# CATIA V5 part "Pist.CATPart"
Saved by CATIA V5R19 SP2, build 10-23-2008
Part number: Pist
Bounding box of the stored display mesh (mm): x -20 to 20, y -20 to 20, z 0 to 180
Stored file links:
  D:\Catia\Flexible-rigid\Pist.CATPart
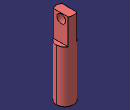
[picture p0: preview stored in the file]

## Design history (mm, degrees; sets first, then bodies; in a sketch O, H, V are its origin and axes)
AxisSystem1: origin (0, 0, 0), X (1, 0, 0), Y (0, 1, 0), Z (0, 0, 1)
Set1
  Sketch1 on XY plane of AxisSystem1, origin (0, 0, 0), H (1, 0, 0), V (0, 1, 0)
    circle A1 centre (0, 0) radius 20
Body1 (main body)
  Pad1: profile Sketch1, direction (0, 0, 1), length 120
  Sketch2 on end face of Pad1, origin (0, 0, 120), H (1, 0, 0), V (0, 1, 0)
    line L1 (10, 17.3205) -> (10, -17.3205)
    line L2 (-10, -17.3205) -> (-10, 17.3205)
    projected circle E1 centre (0, 0) radius 20 from edge [face of Pad1 from Sketch1.A1 | end face of Pad1]
    projected arc E2 centre (0, 0) radius 20 from (10, 17.3205) to (-10, 17.3205) ccw from edge [face of Pad1 from Sketch1.A1 | end face of Pad1]
    projected arc E3 centre (0, 0) radius 20 from (-10, -17.3205) to (10, -17.3205) ccw from edge [face of Pad1 from Sketch1.A1 | end face of Pad1]
    vertical: L1 V, L2 V
  Pad2: profile Sketch2, direction (0, 0, 1), length 60
  Sketch3 on face of Pad2 from Sketch2.L1, origin (10, 1.3642, 138.4248), H (0, 1, 0), V (0, 0, 1)
    point P1 (0, 30)
  Hole1: placed by Sketch3, at (10, 1.3642, 168.4248) direction (-1, 0, 0), diameter 20, through (limit type 6)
